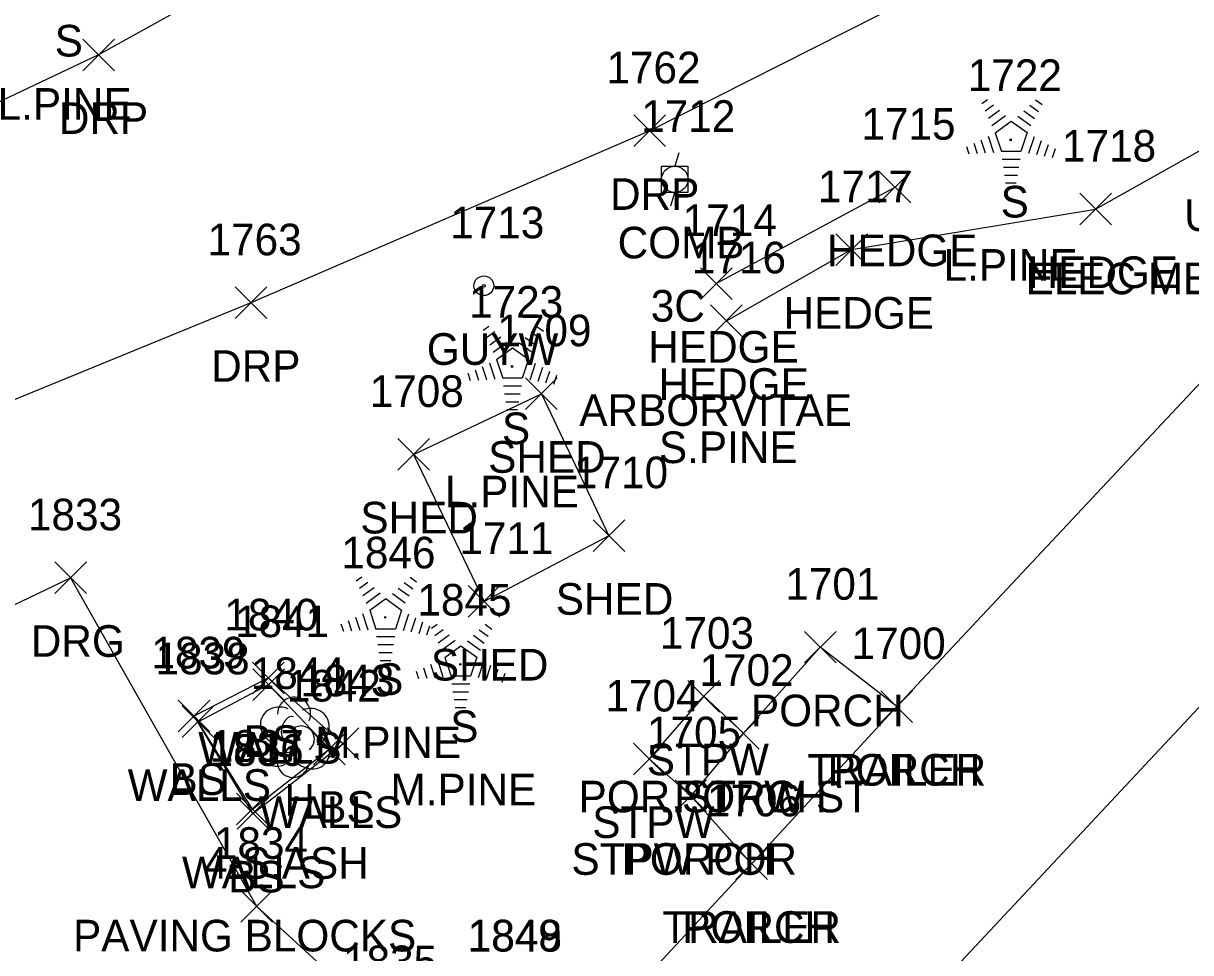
# Model space of a CAD drawing. Extents: x 1477930 to 1480780, y 774090 to 784647.
# Drawn here: x 1479096.5 to 1479170.3, y 774412.2 to 774470.9 of the extents above; entities that cross this region are included whole.
import ezdxf

# ---------------------------------------------------------------- set-up
doc = ezdxf.new("R2010")
doc.units = 0
for name, color, linetype in [('L_A', 7, 'Continuous'), ('L_C', 7, 'Continuous'), ('L_I', 7, 'Continuous'), ('L_TIC', 7, 'Continuous'), ('LAHR', 7, 'Continuous'), ('LBC', 7, 'Continuous'), ('LBF', 7, 'Continuous'), ('LELB', 7, 'Continuous'), ('LTC', 7, 'Continuous'), ('LTD', 7, 'Continuous'), ('LWS', 7, 'Continuous'), ('R_A', 7, 'Continuous'), ('R_I', 7, 'Continuous'), ('R_TIC', 7, 'Continuous'), ('RDG', 7, 'Continuous'), ('RDP', 7, 'Continuous'), ('U_A', 7, 'Continuous'), ('U_C', 7, 'Continuous'), ('U_I', 7, 'Continuous'), ('UP', 7, 'Continuous'), ('UPGW', 7, 'Continuous')]:
    doc.layers.add(name, color=color, linetype=linetype)

msp = doc.modelspace()

# ---------------------------------------------------------------- linework, layer by layer
at = {"layer": 'L_TIC'}
for points in [[(1479150.622, 774459.563), (1479152.622, 774461.563)], [(1479152.622, 774459.563), (1479150.622, 774461.563)], [(1479163.307, 774458.18), (1479165.307, 774460.18)], [(1479165.307, 774458.18), (1479163.307, 774460.18)], [(1479147.872, 774455.612), (1479149.872, 774457.612)], [(1479149.872, 774455.612), (1479147.872, 774457.612)], [(1479139.322, 774453.467), (1479141.322, 774455.467)], [(1479141.322, 774453.467), (1479139.322, 774455.467)], [(1479139.962, 774451.112), (1479141.962, 774453.112)], [(1479141.962, 774451.112), (1479139.962, 774453.112)], [(1479128.26, 774446.501), (1479130.26, 774448.501)], [(1479130.26, 774446.501), (1479128.26, 774448.501)], [(1479120.18, 774442.663), (1479122.18, 774444.663)], [(1479122.18, 774442.663), (1479120.18, 774444.663)], [(1479120.18, 774442.663), (1479122.18, 774444.663)], [(1479122.18, 774442.663), (1479120.18, 774444.663)], [(1479132.535, 774437.522), (1479134.535, 774439.522)], [(1479134.535, 774437.522), (1479132.535, 774439.522)], [(1479124.636, 774433.363), (1479126.636, 774435.363)], [(1479126.636, 774433.363), (1479124.636, 774435.363)], [(1479124.636, 774433.363), (1479126.636, 774435.363)], [(1479126.636, 774433.363), (1479124.636, 774435.363)], [(1479145.892, 774430.471), (1479147.892, 774432.471)], [(1479147.892, 774430.471), (1479145.892, 774432.471)], [(1479110.997, 774428.53), (1479112.997, 774430.53)], [(1479112.997, 774428.53), (1479110.997, 774430.53)], [(1479111.016, 774428.106), (1479113.016, 774430.106)], [(1479113.016, 774428.106), (1479111.016, 774430.106)], [(1479138.528, 774427.37), (1479140.528, 774429.37)], [(1479140.528, 774427.37), (1479138.528, 774429.37)], [(1479150.735, 774426.714), (1479152.735, 774428.714)], [(1479152.735, 774426.714), (1479150.735, 774428.714)], [(1479150.735, 774426.714), (1479152.735, 774428.714)], [(1479152.735, 774426.714), (1479150.735, 774428.714)], [(1479106.305, 774426.127), (1479108.305, 774428.127)], [(1479108.305, 774426.127), (1479106.305, 774428.127)], [(1479106.557, 774425.754), (1479108.557, 774427.754)], [(1479108.557, 774425.754), (1479106.557, 774427.754)], [(1479141.032, 774425.025), (1479143.032, 774427.025)], [(1479143.032, 774425.025), (1479141.032, 774427.025)], [(1479141.032, 774425.025), (1479143.032, 774427.025)], [(1479143.032, 774425.025), (1479141.032, 774427.025)], [(1479115.711, 774424.365), (1479117.711, 774426.365)], [(1479117.711, 774424.365), (1479115.711, 774426.365)], [(1479115.711, 774424.365), (1479117.711, 774426.365)], [(1479117.711, 774424.365), (1479115.711, 774426.365)], [(1479114.855, 774424.036), (1479116.855, 774426.036)], [(1479116.855, 774424.036), (1479114.855, 774426.036)], [(1479114.855, 774424.036), (1479116.855, 774426.036)], [(1479116.855, 774424.036), (1479114.855, 774426.036)], [(1479135.086, 774423.405), (1479137.086, 774425.405)], [(1479137.086, 774423.405), (1479135.086, 774425.405)], [(1479137.712, 774421.077), (1479139.712, 774423.077)], [(1479139.712, 774421.077), (1479137.712, 774423.077)], [(1479137.712, 774421.077), (1479139.712, 774423.077)], [(1479139.712, 774421.077), (1479137.712, 774423.077)], [(1479109.989, 774420.231), (1479111.989, 774422.231)], [(1479111.989, 774420.231), (1479109.989, 774422.231)], [(1479109.989, 774420.231), (1479111.989, 774422.231)], [(1479111.989, 774420.231), (1479109.989, 774422.231)], [(1479110.027, 774419.961), (1479112.027, 774421.961)], [(1479112.027, 774419.961), (1479110.027, 774421.961)], [(1479110.027, 774419.961), (1479112.027, 774421.961)], [(1479112.027, 774419.961), (1479110.027, 774421.961)], [(1479141.552, 774416.774), (1479143.552, 774418.774)], [(1479143.552, 774416.774), (1479141.552, 774418.774)], [(1479141.552, 774416.774), (1479143.552, 774418.774)], [(1479143.552, 774416.774), (1479141.552, 774418.774)]]:
    msp.add_lwpolyline(points, dxfattribs=at)
at = {"layer": 'LAHR'}
for points in [[(1479140.962, 774452.112), (1479148.872, 774456.612), (1479164.307, 774459.18), (1479176.454, 774466.01)], [(1479140.322, 774454.467), (1479151.622, 774460.563)]]:
    msp.add_lwpolyline(points, dxfattribs=at)
at = {"layer": 'LBC'}
for points in [[(1479187.686, 774445.679), (1479177.374, 774455.051), (1479151.735, 774427.714), (1479142.552, 774417.774), (1479132.185, 774406.626), (1479142.278, 774397.124)], [(1479121.18, 774443.663), (1479129.26, 774447.501), (1479133.535, 774438.522), (1479125.636, 774434.363)], [(1479187.686, 774445.679), (1479142.278, 774397.124)], [(1479121.18, 774443.663), (1479125.636, 774434.363)]]:
    msp.add_lwpolyline(points, dxfattribs=at)
at = {"layer": 'LBF'}
for points in [[(1479151.735, 774427.714), (1479146.892, 774431.471), (1479142.032, 774426.025), (1479138.712, 774422.077), (1479142.552, 774417.774)], [(1479142.032, 774426.025), (1479139.528, 774428.37), (1479136.086, 774424.405), (1479138.712, 774422.077)]]:
    msp.add_lwpolyline(points, dxfattribs=at)
at = {"layer": 'LELB'}
for points in [[(1479111.027, 774420.961), (1479107.305, 774427.127), (1479111.997, 774429.53), (1479116.711, 774425.365)], [(1479111.027, 774420.961), (1479116.711, 774425.365)]]:
    msp.add_lwpolyline(points, dxfattribs=at)
at = {"layer": 'LTC'}
for p, q in [((1479157.111, 774465.852), (1479157.465, 774466.11)), ((1479160.509, 774466.093), (1479160.928, 774465.788)), ((1479157.32, 774465.387), (1479157.849, 774465.771)), ((1479157.53, 774464.921), (1479158.233, 774465.432)), ((1479159.767, 774465.396), (1479160.446, 774464.902)), ((1479160.138, 774465.744), (1479160.687, 774465.345)), ((1479157.739, 774464.455), (1479158.618, 774465.093)), ((1479157.964, 774464), (1479158.976, 774464.735)), ((1479158.976, 774464.735), (1479159.973, 774464.01)), ((1479159.396, 774465.048), (1479160.205, 774464.459)), ((1479157.964, 774464), (1479158.351, 774462.807)), ((1479159.973, 774464.01), (1479159.581, 774462.807)), ((1479156.143, 774463.132), (1479156.295, 774462.664)), ((1479156.598, 774463.348), (1479156.81, 774462.697)), ((1479157.054, 774463.565), (1479157.325, 774462.729)), ((1479157.509, 774463.781), (1479157.84, 774462.762)), ((1479160.41, 774463.739), (1479160.072, 774462.699)), ((1479160.855, 774463.489), (1479160.567, 774462.604)), ((1479161.299, 774463.239), (1479161.062, 774462.509)), ((1479159.581, 774462.807), (1479158.351, 774462.807)), ((1479161.743, 774462.988), (1479161.557, 774462.414)), ((1479159.543, 774462.307), (1479158.398, 774462.307)), ((1479159.459, 774461.807), (1479158.471, 774461.807)), ((1479159.376, 774461.307), (1479158.544, 774461.307)), ((1479159.292, 774460.807), (1479158.617, 774460.807)), ((1479125.579, 774451.518), (1479125.933, 774451.776)), ((1479125.788, 774451.053), (1479126.317, 774451.437)), ((1479128.606, 774451.41), (1479129.155, 774451.011)), ((1479128.977, 774451.759), (1479129.396, 774451.454)), ((1479125.998, 774450.587), (1479126.701, 774451.098)), ((1479126.207, 774450.121), (1479127.086, 774450.759)), ((1479127.864, 774450.714), (1479128.673, 774450.125)), ((1479128.235, 774451.062), (1479128.914, 774450.568)), ((1479126.432, 774449.666), (1479127.444, 774450.401)), ((1479127.444, 774450.401), (1479128.441, 774449.676)), ((1479125.522, 774449.231), (1479125.793, 774448.395)), ((1479125.977, 774449.447), (1479126.308, 774448.428)), ((1479126.432, 774449.666), (1479126.819, 774448.473)), ((1479128.441, 774449.676), (1479128.049, 774448.473)), ((1479128.878, 774449.405), (1479128.54, 774448.365)), ((1479129.323, 774449.155), (1479129.035, 774448.27)), ((1479124.611, 774448.797), (1479124.763, 774448.33)), ((1479125.066, 774449.014), (1479125.278, 774448.362)), ((1479128.049, 774448.473), (1479126.819, 774448.473)), ((1479129.767, 774448.905), (1479129.53, 774448.175)), ((1479130.211, 774448.654), (1479130.025, 774448.08)), ((1479128.011, 774447.973), (1479126.866, 774447.973)), ((1479127.927, 774447.473), (1479126.939, 774447.473)), ((1479127.844, 774446.973), (1479127.012, 774446.973)), ((1479127.76, 774446.473), (1479127.085, 774446.473)), ((1479117.558, 774435.662), (1479117.913, 774435.92)), ((1479120.957, 774435.903), (1479121.376, 774435.598)), ((1479117.768, 774435.197), (1479118.297, 774435.581)), ((1479117.977, 774434.731), (1479118.681, 774435.242)), ((1479120.214, 774435.206), (1479120.894, 774434.712)), ((1479120.585, 774435.554), (1479121.135, 774435.155)), ((1479118.187, 774434.265), (1479119.065, 774434.903)), ((1479118.412, 774433.81), (1479119.423, 774434.545)), ((1479119.423, 774434.545), (1479120.42, 774433.82)), ((1479119.843, 774434.858), (1479120.653, 774434.269)), ((1479117.957, 774433.591), (1479118.288, 774432.572)), ((1479118.412, 774433.81), (1479118.799, 774432.617)), ((1479120.42, 774433.82), (1479120.029, 774432.617)), ((1479120.858, 774433.549), (1479120.52, 774432.509)), ((1479116.591, 774432.942), (1479116.743, 774432.474)), ((1479117.046, 774433.158), (1479117.258, 774432.507)), ((1479117.502, 774433.375), (1479117.773, 774432.539)), ((1479121.302, 774433.299), (1479121.015, 774432.414)), ((1479121.747, 774433.049), (1479121.51, 774432.319)), ((1479122.191, 774432.798), (1479122.004, 774432.224)), ((1479122.311, 774432.677), (1479122.666, 774432.935)), ((1479125.709, 774432.918), (1479126.128, 774432.613)), ((1479120.029, 774432.617), (1479118.799, 774432.617)), ((1479119.991, 774432.117), (1479118.846, 774432.117)), ((1479122.521, 774432.212), (1479123.05, 774432.596)), ((1479122.73, 774431.746), (1479123.434, 774432.257)), ((1479124.967, 774432.221), (1479125.646, 774431.727)), ((1479125.338, 774432.569), (1479125.888, 774432.17)), ((1479119.907, 774431.617), (1479118.919, 774431.617)), ((1479122.94, 774431.28), (1479123.818, 774431.918)), ((1479123.164, 774430.825), (1479124.176, 774431.56)), ((1479124.176, 774431.56), (1479125.173, 774430.835)), ((1479124.596, 774431.873), (1479125.406, 774431.284)), ((1479119.823, 774431.117), (1479118.992, 774431.117)), ((1479119.739, 774430.617), (1479119.064, 774430.617)), ((1479122.71, 774430.606), (1479123.041, 774429.587)), ((1479123.164, 774430.825), (1479123.551, 774429.632)), ((1479125.173, 774430.835), (1479124.782, 774429.632)), ((1479121.343, 774429.956), (1479121.496, 774429.489)), ((1479121.799, 774430.173), (1479122.011, 774429.521)), ((1479122.254, 774430.39), (1479122.526, 774429.554)), ((1479125.611, 774430.564), (1479125.273, 774429.524)), ((1479126.055, 774430.314), (1479125.768, 774429.429)), ((1479126.5, 774430.064), (1479126.263, 774429.334)), ((1479124.782, 774429.632), (1479123.551, 774429.632)), ((1479124.743, 774429.132), (1479123.599, 774429.132)), ((1479126.944, 774429.813), (1479126.757, 774429.239)), ((1479124.66, 774428.632), (1479123.671, 774428.632)), ((1479124.576, 774428.132), (1479123.744, 774428.132)), ((1479124.492, 774427.632), (1479123.817, 774427.632))]:
    msp.add_line(p, q, dxfattribs=at)
at = {"layer": 'LTD'}
msp.add_line((1479113.58, 774425.825), (1479113.58, 774425.825), dxfattribs=at)
msp.add_line((1479113.58, 774425.825), (1479113.58, 774425.825), dxfattribs=at)
msp.add_arc((1479113.627, 774427.259), 1.047, 335.52715, 180.95627, dxfattribs=at)
for centre, major_axis, ratio, start_param, end_param in [((1479112.788, 774426.491), (1.21, -0.512), 0.895232, 1.570796, 4.712389), ((1479114.621, 774426.408), (-1.141, -0.483), 0.949671, 1.570796, 4.712389), ((1479113.371, 774426.283), (-0.208, -0.792), 0.645439, 3.141593, 6.283185), ((1479112.497, 774425.116), (0.584, -1.042), 0.959034, 3.141593, 6.283185), ((1479114.08, 774425.658), (-0.5, 0.667), 0.989748, 3.141593, 6.283185), ((1479114.58, 774424.992), (-1.09, 0.792), 0.841452, 1.570796, 4.712389), ((1479113.122, 774425.075), (-0.625, -0.083), 0.423636, 0, 3.141593), ((1479113.58, 774424.325), (0.265, 1.061), 0.942809, 1.570796, 4.712389)]:
    msp.add_ellipse(centre, major_axis=major_axis, ratio=ratio, start_param=start_param, end_param=end_param, dxfattribs=at)
at = {"layer": 'LWS'}
for points in [[(1479110.989, 774421.231), (1479107.557, 774426.754), (1479112.016, 774429.106), (1479115.855, 774425.036)], [(1479110.989, 774421.231), (1479115.855, 774425.036)]]:
    msp.add_lwpolyline(points, dxfattribs=at)
at = {"layer": 'R_TIC'}
for points in [[(1479100.265, 774467.925), (1479102.265, 774469.925)], [(1479102.265, 774467.925), (1479100.265, 774469.925)], [(1479135.115, 774463.126), (1479137.115, 774465.126)], [(1479137.115, 774463.126), (1479135.115, 774465.126)], [(1479109.894, 774452.252), (1479111.894, 774454.252)], [(1479111.894, 774452.252), (1479109.894, 774454.252)], [(1479098.491, 774434.861), (1479100.491, 774436.861)], [(1479100.491, 774434.861), (1479098.491, 774436.861)], [(1479110.25, 774414.085), (1479112.25, 774416.085)], [(1479112.25, 774414.085), (1479110.25, 774416.085)]]:
    msp.add_lwpolyline(points, dxfattribs=at)
at = {"layer": 'RDG'}
msp.add_lwpolyline([(1479000.285, 774404.185), (1479014.659, 774390.047), (1479047.464, 774386.408), (1479082.424, 774397.913), (1479092.78, 774404.139), (1479080.31, 774426.656), (1479099.491, 774435.861), (1479111.25, 774415.085), (1479119.414, 774407.602), (1479089.107, 774388.499), (1479108.735, 774376.691), (1479096.509, 774359.631), (1479079.071, 774370.658), (1479068.454, 774377.31), (1479035.786, 774371.215), (1479007.425, 774376.712), (1478987.908, 774394.732)], dxfattribs=at)
at = {"layer": 'RDP'}
for points in [[(1479196.157, 774549.722), (1479150.608, 774530.18), (1479100.702, 774505.669), (1479114.057, 774476.034), (1479101.265, 774468.925), (1479068.733, 774453.512), (1479023.572, 774433.612), (1478990.24, 774425.08), (1478973.522, 774441.237), (1478963.537, 774465.835), (1478965.909, 774472.744)], [(1479362.085, 774490.122), (1479342.053, 774496.544), (1479325.922, 774501.653), (1479312.309, 774505.809), (1479281.235, 774507.912), (1479260.189, 774507.512), (1479228.518, 774504.276), (1479173.381, 774482.974), (1479136.115, 774464.126), (1479110.894, 774453.252), (1479073.731, 774438.018), (1479028.367, 774422.341), (1479014.067, 774419.453), (1479003.406, 774415.123), (1479000.285, 774404.185), (1478987.908, 774394.732), (1478976.965, 774410.388), (1478964.404, 774425.192), (1478951.82, 774441.875), (1478940.933, 774454.02), (1478935.821, 774456.705)]]:
    msp.add_lwpolyline(points, dxfattribs=at)
at = {"layer": 'UP'}
for p, q in [((1479137.949, 774462.724), (1479137.699, 774461.891)), ((1479136.865, 774460.224), (1479136.865, 774461.891)), ((1479136.865, 774461.891), (1479138.532, 774461.891)), ((1479138.532, 774461.891), (1479138.532, 774460.224)), ((1479137.699, 774461.058), (1479137.699, 774461.058)), ((1479138.532, 774460.224), (1479136.865, 774460.224)), ((1479137.449, 774459.391), (1479137.699, 774460.224))]:
    msp.add_line(p, q, dxfattribs=at)
msp.add_circle((1479137.699, 774461.058), 0.833, dxfattribs=at)
at = {"layer": 'UPGW'}
for radius in [0.625, 0.0833]:
    msp.add_circle((1479125.624, 774454.326), radius, dxfattribs=at)

# ---------------------------------------------------------------- texts
at = {"layer": 'L_A'}
for s, p in [('S', (1479098.488, 774468.825)), ('S', (1479158.301, 774458.644)), ('HEDGE', (1479147.323, 774455.563)), ('HEDGE', (1479160.007, 774454.18)), ('HEDGE', (1479144.573, 774451.612)), ('HEDGE', (1479136.023, 774449.467)), ('HEDGE', (1479136.663, 774447.112)), ('S', (1479126.769, 774444.31)), ('SHED', (1479125.897, 774442.501)), ('SHED', (1479117.818, 774438.663)), ('SHED', (1479117.818, 774438.663)), ('SHED', (1479130.173, 774433.522)), ('SHED', (1479122.274, 774429.363)), ('SHED', (1479122.274, 774429.363)), ('S', (1479118.749, 774428.454)), ('PORCH', (1479142.514, 774426.471)), ('S', (1479123.502, 774425.469)), ('BS', (1479110.438, 774424.53)), ('WALLS', (1479107.56, 774424.106)), ('STPW', (1479135.922, 774423.37)), ('TRAILER', (1479146.09, 774422.714)), ('PORCH', (1479147.357, 774422.714)), ('BS', (1479105.746, 774422.127)), ('WALLS', (1479103.101, 774421.754)), ('H', (1479113.013, 774420.825)), ('POR STPW ST', (1479131.615, 774421.025)), ('PORCH', (1479137.654, 774421.025)), ('WALLS', (1479111.398, 774420.036)), ('WALLS', (1479111.398, 774420.036)), ('BS', (1479115.152, 774420.365)), ('BS', (1479115.152, 774420.365)), ('STPW', (1479132.48, 774419.405)), ('STPW POR', (1479131.161, 774417.077)), ('PORCH', (1479134.334, 774417.077)), ('WALLS', (1479106.532, 774416.231)), ('WALLS', (1479106.532, 774416.231)), ('BS', (1479109.468, 774415.961)), ('BS', (1479109.468, 774415.961)), ('TRAILER', (1479136.907, 774412.774)), ('PORCH', (1479138.174, 774412.774))]:
    msp.add_text(s, height=2, dxfattribs=at).set_placement(p)
at = {"layer": 'L_C'}
for s, p in [('L.PINE', (1479094.882, 774464.825)), ('L.PINE', (1479154.695, 774454.644)), ('ARBORVITAE', (1479131.661, 774445.467)), ('S.PINE', (1479136.694, 774443.112)), ('L.PINE', (1479123.163, 774440.31)), ('M.PINE', (1479114.969, 774424.454)), ('M.PINE', (1479119.722, 774421.469)), ('4-S.ASH', (1479107.942, 774416.825)), ('PAVING BLOCKS', (1479099.65, 774412.231)), ('PAVING BLOCKS', (1479099.65, 774412.231))]:
    msp.add_text(s, height=2, dxfattribs=at).set_placement(p)
at = {"layer": 'L_I'}
for s, p in [('1722', (1479156.222, 774466.644)), ('1715', (1479149.496, 774463.563)), ('1718', (1479162.181, 774462.18)), ('1717', (1479146.746, 774459.612)), ('1714', (1479138.196, 774457.467)), ('1716', (1479138.781, 774455.112)), ('1723', (1479124.69, 774452.31)), ('1709', (1479126.48, 774450.501)), ('1708', (1479118.408, 774446.663)), ('1708', (1479118.408, 774446.663)), ('1710', (1479131.323, 774441.522)), ('1711', (1479124.077, 774437.363)), ('1711', (1479124.077, 774437.363)), ('1846', (1479116.615, 774436.454)), ('1701', (1479144.687, 774434.471)), ('1845', (1479121.423, 774433.469)), ('1840', (1479109.218, 774432.53)), ('1841', (1479109.891, 774432.106)), ('1703', (1479136.757, 774431.37)), ('1839', (1479104.604, 774430.127)), ('1700', (1479148.877, 774430.714)), ('1700', (1479148.877, 774430.714)), ('1838', (1479104.864, 774429.754)), ('1844', (1479110.887, 774428.825)), ('1702', (1479139.261, 774429.025)), ('1702', (1479139.261, 774429.025)), ('1842', (1479113.162, 774428.036)), ('1842', (1479113.162, 774428.036)), ('1843', (1479114.018, 774428.365)), ('1843', (1479114.018, 774428.365)), ('1704', (1479133.314, 774427.405)), ('1705', (1479135.94, 774425.077)), ('1705', (1479135.94, 774425.077)), ('1837', (1479108.296, 774424.231)), ('1837', (1479108.296, 774424.231)), ('1836', (1479108.279, 774423.961)), ('1836', (1479108.279, 774423.961)), ('1706', (1479139.725, 774420.774)), ('1706', (1479139.725, 774420.774)), ('1849', (1479124.596, 774412.235)), ('1848', (1479124.617, 774412.221))]:
    msp.add_text(s, height=2, dxfattribs=at).set_placement(p)
at = {"layer": 'LTC'}
for p in [(1479158.858, 774463.748), (1479127.326, 774449.414), (1479119.306, 774433.558), (1479124.058, 774430.573)]:
    msp.add_text('.', height=1.037, rotation=270, dxfattribs=at).set_placement(p)
at = {"layer": 'R_A'}
for s, p in [('DRP', (1479098.753, 774463.925)), ('DRP', (1479133.603, 774459.126)), ('DRP', (1479108.383, 774448.252)), ('DRG', (1479096.979, 774430.861))]:
    msp.add_text(s, height=2, dxfattribs=at).set_placement(p)
at = {"layer": 'R_I'}
for s, p in [('1762', (1479133.375, 774467.126)), ('1763', (1479108.154, 774456.252)), ('1833', (1479096.798, 774438.861)), ('1834', (1479108.557, 774418.085)), ('1835', (1479116.721, 774410.602))]:
    msp.add_text(s, height=2, dxfattribs=at).set_placement(p)
at = {"layer": 'U_A'}
for s, p in [('UTIL', (1479169.906, 774457.789)), ('COMB', (1479134.084, 774456.058)), ('GUYW', (1479122.018, 774449.326))]:
    msp.add_text(s, height=2, dxfattribs=at).set_placement(p)
at = {"layer": 'U_C'}
for s, p in [('ELEC METER BOX', (1479159.875, 774453.789)), ('3C', (1479136.179, 774452.058))]:
    msp.add_text(s, height=2, dxfattribs=at).set_placement(p)
at = {"layer": 'U_I'}
for s, p in [('1712', (1479135.573, 774464.058)), ('1713', (1479123.498, 774457.326))]:
    msp.add_text(s, height=2, dxfattribs=at).set_placement(p)

doc.saveas('drawing.dxf')
